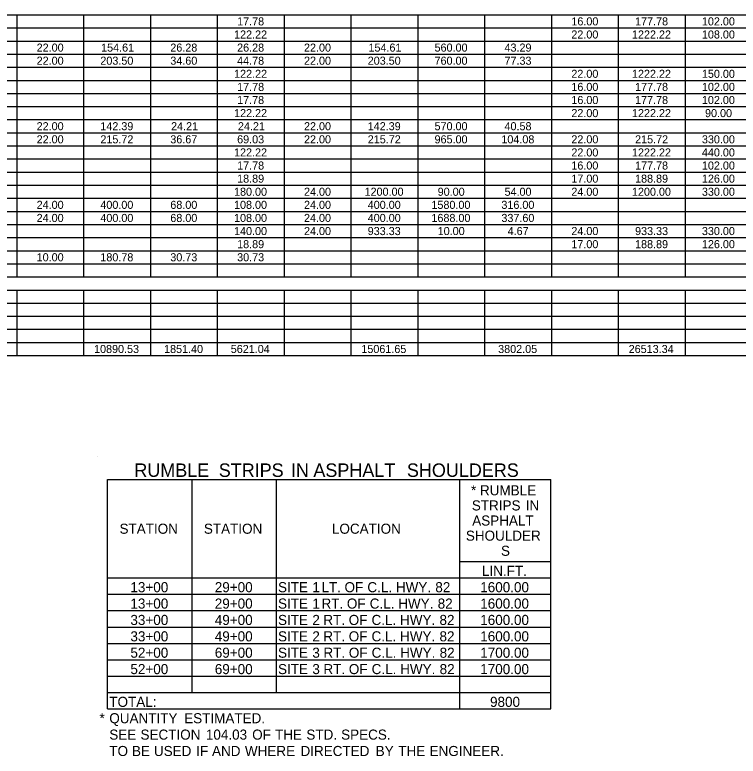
# Model space of a CAD drawing. Extents: x 977434 to 989596, y 1525697 to 1528336.
# Drawn here: x 983226 to 983656.5, y 1527372 to 1527813.2 of the extents above; entities that cross this region are included whole.
import ezdxf

# ---------------------------------------------------------------- set-up
doc = ezdxf.new("R2010")
doc.units = 0
doc.layers.add('Default', color=7, linetype='Continuous')
doc.layers.add('R_Border Prem', color=7, linetype='Continuous')

msp = doc.modelspace()

# ---------------------------------------------------------------- linework, layer by layer
at = {"layer": 'Default'}
for p, q in [((982704.74, 1527813.24), (984062.72, 1527813.24)), ((983227.34, 1527657.24), (983227.34, 1527813.24)), ((983227.34, 1527657.24), (983227.34, 1527813.24)), ((983267.12, 1527657.24), (983267.12, 1527813.24)), ((983267.12, 1527657.24), (983267.12, 1527813.24)), ((983306.9, 1527657.24), (983306.9, 1527813.24)), ((983306.9, 1527657.24), (983306.9, 1527813.24)), ((983346.68, 1527657.24), (983346.68, 1527813.24)), ((983346.68, 1527657.24), (983346.68, 1527813.24)), ((983386.46, 1527657.24), (983386.46, 1527813.24)), ((983386.46, 1527657.24), (983386.46, 1527813.24)), ((983426.24, 1527657.24), (983426.24, 1527813.24)), ((983426.24, 1527657.24), (983426.24, 1527813.24)), ((983466.02, 1527657.24), (983466.02, 1527813.24)), ((983466.02, 1527657.24), (983466.02, 1527813.24)), ((983505.8, 1527657.24), (983505.8, 1527813.24)), ((983505.8, 1527657.24), (983505.8, 1527813.24)), ((983545.58, 1527657.24), (983545.58, 1527813.24)), ((983545.58, 1527657.24), (983545.58, 1527813.24)), ((983585.36, 1527657.24), (983585.36, 1527813.24)), ((983585.36, 1527657.24), (983585.36, 1527813.24)), ((983625.14, 1527657.24), (983625.14, 1527813.24)), ((983625.14, 1527657.24), (983625.14, 1527813.24)), ((982704.74, 1527805.44), (984062.72, 1527805.44)), ((982704.74, 1527797.64), (984062.72, 1527797.64)), ((982704.74, 1527789.84), (984062.72, 1527789.84)), ((982704.74, 1527782.04), (984062.72, 1527782.04)), ((982704.74, 1527774.24), (984062.72, 1527774.24)), ((982704.74, 1527766.44), (984062.72, 1527766.44)), ((982704.74, 1527758.64), (984062.72, 1527758.64)), ((982704.74, 1527750.84), (984062.72, 1527750.84)), ((982704.74, 1527743.04), (984062.72, 1527743.04)), ((982704.74, 1527735.24), (984062.72, 1527735.24)), ((982704.74, 1527727.44), (984062.72, 1527727.44)), ((982704.74, 1527719.64), (984062.72, 1527719.64)), ((982704.74, 1527711.84), (984062.72, 1527711.84)), ((982704.74, 1527704.04), (984062.72, 1527704.04)), ((982704.74, 1527696.24), (984062.72, 1527696.24)), ((982704.74, 1527688.44), (984062.72, 1527688.44)), ((982704.74, 1527680.64), (984062.72, 1527680.64)), ((982704.74, 1527672.84), (984062.72, 1527672.84)), ((982704.74, 1527665.04), (984062.72, 1527665.04)), ((982704.74, 1527657.24), (984062.72, 1527657.24)), ((983108, 1527657.24), (983346.68, 1527657.24)), ((983346.68, 1527657.24), (983903.6, 1527657.24)), ((982704.74, 1527649.44), (984062.72, 1527649.44)), ((983227.34, 1527610.44), (983227.34, 1527649.44)), ((983227.34, 1527610.44), (983227.34, 1527649.44)), ((983267.12, 1527610.44), (983267.12, 1527649.44)), ((983267.12, 1527610.44), (983267.12, 1527649.44)), ((983306.9, 1527610.44), (983306.9, 1527649.44)), ((983306.9, 1527610.44), (983306.9, 1527649.44)), ((983346.68, 1527610.44), (983346.68, 1527649.44)), ((983346.68, 1527610.44), (983346.68, 1527649.44)), ((983386.46, 1527610.44), (983386.46, 1527649.44)), ((983386.46, 1527610.44), (983386.46, 1527649.44)), ((983426.24, 1527610.44), (983426.24, 1527649.44)), ((983426.24, 1527610.44), (983426.24, 1527649.44)), ((983466.02, 1527610.44), (983466.02, 1527649.44)), ((983466.02, 1527610.44), (983466.02, 1527649.44)), ((983505.8, 1527618.24), (983505.8, 1527649.44)), ((983505.8, 1527610.44), (983505.8, 1527649.44)), ((983545.58, 1527610.44), (983545.58, 1527649.44)), ((983545.58, 1527610.44), (983545.58, 1527649.44)), ((983585.36, 1527610.44), (983585.36, 1527649.44)), ((983585.36, 1527610.44), (983585.36, 1527649.44)), ((983625.14, 1527610.44), (983625.14, 1527649.44)), ((983625.14, 1527610.44), (983625.14, 1527649.44)), ((982704.74, 1527641.64), (984062.72, 1527641.64)), ((982704.74, 1527633.84), (984062.72, 1527633.84)), ((982704.74, 1527626.04), (984062.72, 1527626.04)), ((982704.74, 1527618.24), (984062.72, 1527618.24)), ((982704.74, 1527610.44), (984062.72, 1527610.44)), ((983281.27, 1527536.61), (983545.01, 1527536.61)), ((983281.27, 1527400.11), (983281.27, 1527536.61)), ((983281.27, 1527400.11), (983281.27, 1527536.61)), ((983331.49, 1527409.86), (983331.49, 1527536.61)), ((983331.49, 1527409.86), (983331.49, 1527536.61)), ((983381.7, 1527409.86), (983381.7, 1527536.61)), ((983381.7, 1527409.86), (983381.7, 1527536.61)), ((983490.9, 1527400.11), (983490.9, 1527536.61)), ((983545.01, 1527400.11), (983545.01, 1527536.61)), ((983545.01, 1527400.11), (983545.01, 1527536.61)), ((983490.9, 1527487.86), (983545.01, 1527487.86)), ((983281.27, 1527478.11), (983545.01, 1527478.11)), ((983281.27, 1527468.36), (983545.01, 1527468.36)), ((983281.27, 1527458.61), (983545.01, 1527458.61)), ((983281.27, 1527448.86), (983545.01, 1527448.86)), ((983281.27, 1527439.11), (983545.01, 1527439.11)), ((983281.27, 1527429.36), (983545.01, 1527429.36)), ((983281.27, 1527419.61), (983545.01, 1527419.61)), ((983281.27, 1527409.86), (983490.9, 1527409.86)), ((983281.27, 1527409.86), (983381.7, 1527409.86)), ((983381.7, 1527409.86), (983545.01, 1527409.86)), ((983281.27, 1527400.11), (983545.01, 1527400.11))]:
    msp.add_line(p, q, dxfattribs=at)
at = {"layer": 'R_Border Prem'}
msp.add_line((983275.42, 1527550.26), (983275.42, 1527550.26), dxfattribs=at)

# ---------------------------------------------------------------- texts
at = {"layer": 'Default'}
for s, height, p in [('17.78', 4.8, (983358.33, 1527806.94)), ('16.00', 4.8, (983557.24, 1527806.94)), ('177.78', 4.8, (983595.15, 1527806.94)), ('102.00', 4.8, (983634.94, 1527806.94)), ('122.22', 4.8, (983356.5, 1527799.14)), ('22.00', 4.8, (983557.24, 1527799.14)), ('1222.22', 4.8, (983593.31, 1527799.14)), ('108.00', 4.8, (983634.94, 1527799.14)), ('22.00', 4.8, (983239, 1527791.34)), ('154.61', 4.8, (983277.37, 1527791.34)), ('26.28', 4.8, (983318.55, 1527791.34)), ('26.28', 4.8, (983358.33, 1527791.34)), ('22.00', 4.8, (983398.12, 1527791.34)), ('154.61', 4.8, (983436.49, 1527791.34)), ('560.00', 4.8, (983475.82, 1527791.34)), ('43.29', 4.8, (983517.45, 1527791.34)), ('22.00', 4.8, (983239, 1527783.54)), ('203.50', 4.8, (983276.92, 1527783.54)), ('34.60', 4.8, (983318.56, 1527783.54)), ('44.78', 4.8, (983358.33, 1527783.54)), ('22.00', 4.8, (983398.12, 1527783.54)), ('203.50', 4.8, (983436.04, 1527783.54)), ('760.00', 4.8, (983475.82, 1527783.54)), ('77.33', 4.8, (983517.45, 1527783.54)), ('122.22', 4.8, (983356.5, 1527775.74)), ('22.00', 4.8, (983557.24, 1527775.74)), ('1222.22', 4.8, (983593.31, 1527775.74)), ('150.00', 4.8, (983634.94, 1527775.74)), ('17.78', 4.8, (983358.33, 1527767.94)), ('16.00', 4.8, (983557.24, 1527767.94)), ('177.78', 4.8, (983595.15, 1527767.94)), ('102.00', 4.8, (983634.94, 1527767.94)), ('17.78', 4.8, (983358.33, 1527760.14)), ('16.00', 4.8, (983557.24, 1527760.14)), ('177.78', 4.8, (983595.15, 1527760.14)), ('102.00', 4.8, (983634.94, 1527760.14)), ('122.22', 4.8, (983356.5, 1527752.34)), ('22.00', 4.8, (983557.24, 1527752.34)), ('1222.22', 4.8, (983593.31, 1527752.34)), ('90.00', 4.8, (983636.8, 1527752.34)), ('22.00', 4.8, (983239, 1527744.54)), ('142.39', 4.8, (983276.91, 1527744.54)), ('24.21', 4.8, (983319.02, 1527744.54)), ('24.21', 4.8, (983358.8, 1527744.54)), ('22.00', 4.8, (983398.12, 1527744.54)), ('142.39', 4.8, (983436.03, 1527744.54)), ('570.00', 4.8, (983475.82, 1527744.54)), ('40.58', 4.8, (983517.45, 1527744.54)), ('22.00', 4.8, (983239, 1527736.74)), ('215.72', 4.8, (983276.94, 1527736.74)), ('36.67', 4.8, (983318.55, 1527736.74)), ('69.03', 4.8, (983358.33, 1527736.74)), ('22.00', 4.8, (983398.12, 1527736.74)), ('215.72', 4.8, (983436.06, 1527736.74)), ('965.00', 4.8, (983475.82, 1527736.74)), ('104.08', 4.8, (983515.59, 1527736.74)), ('22.00', 4.8, (983557.24, 1527736.74)), ('215.72', 4.8, (983595.18, 1527736.74)), ('330.00', 4.8, (983634.94, 1527736.74)), ('122.22', 4.8, (983356.5, 1527728.94)), ('22.00', 4.8, (983557.24, 1527728.94)), ('1222.22', 4.8, (983593.31, 1527728.94)), ('440.00', 4.8, (983634.94, 1527728.94)), ('17.78', 4.8, (983358.33, 1527721.14)), ('16.00', 4.8, (983557.24, 1527721.14)), ('177.78', 4.8, (983595.15, 1527721.14)), ('102.00', 4.8, (983634.94, 1527721.14)), ('18.89', 4.8, (983358.33, 1527713.34)), ('17.00', 4.8, (983557.24, 1527713.34)), ('188.89', 4.8, (983595.15, 1527713.34)), ('126.00', 4.8, (983634.94, 1527713.34)), ('180.00', 4.8, (983356.48, 1527705.54)), ('24.00', 4.8, (983398.12, 1527705.54)), ('1200.00', 4.8, (983434.18, 1527705.54)), ('90.00', 4.8, (983477.68, 1527705.54)), ('54.00', 4.8, (983517.46, 1527705.54)), ('24.00', 4.8, (983557.24, 1527705.54)), ('1200.00', 4.8, (983593.3, 1527705.54)), ('330.00', 4.8, (983634.94, 1527705.54)), ('24.00', 4.8, (983239, 1527697.74)), ('400.00', 4.8, (983276.92, 1527697.74)), ('68.00', 4.8, (983318.56, 1527697.74)), ('108.00', 4.8, (983356.48, 1527697.74)), ('24.00', 4.8, (983398.12, 1527697.74)), ('400.00', 4.8, (983436.04, 1527697.74)), ('1580.00', 4.8, (983473.96, 1527697.74)), ('316.00', 4.8, (983515.6, 1527697.74)), ('24.00', 4.8, (983239, 1527689.94)), ('400.00', 4.8, (983276.92, 1527689.94)), ('68.00', 4.8, (983318.56, 1527689.94)), ('108.00', 4.8, (983356.48, 1527689.94)), ('24.00', 4.8, (983398.12, 1527689.94)), ('400.00', 4.8, (983436.04, 1527689.94)), ('1688.00', 4.8, (983473.96, 1527689.94)), ('337.60', 4.8, (983515.6, 1527689.94)), ('140.00', 4.8, (983356.48, 1527682.14)), ('24.00', 4.8, (983398.12, 1527682.14)), ('933.33', 4.8, (983436.03, 1527682.14)), ('10.00', 4.8, (983477.68, 1527682.14)), ('4.67', 4.8, (983519.32, 1527682.14)), ('24.00', 4.8, (983557.24, 1527682.14)), ('933.33', 4.8, (983595.15, 1527682.14)), ('330.00', 4.8, (983634.94, 1527682.14)), ('18.89', 4.8, (983358.33, 1527674.34)), ('17.00', 4.8, (983557.24, 1527674.34)), ('188.89', 4.8, (983595.15, 1527674.34)), ('126.00', 4.8, (983634.94, 1527674.34)), ('10.00', 4.8, (983239, 1527666.54)), ('180.78', 4.8, (983276.91, 1527666.54)), ('30.73', 4.8, (983318.55, 1527666.54)), ('30.73', 4.8, (983358.33, 1527666.54)), ('10890.53', 4.8, (983273.17, 1527611.94)), ('1851.40', 4.8, (983314.84, 1527611.94)), ('5621.04', 4.8, (983354.53, 1527611.94)), ('15061.65', 4.8, (983432.25, 1527611.94)), ('3802.05', 4.8, (983513.68, 1527611.94)), ('26513.34', 4.8, (983591.35, 1527611.94)), ('RUMBLE', 8, (983297.15, 1527538.21)), (' STRIPS', 8, (983344.41, 1527538.21)), (' IN', 8, (983387.34, 1527538.21)), (' ASPHALT', 8, (983400.73, 1527538.21)), (' SHOULDERS', 8, (983456.39, 1527538.21)), ('*', 6, (983497.53, 1527527.23)), (' RUMBLE', 6, (983500.61, 1527527.23)), ('STRIPS', 6, (983498, 1527518.23)), (' IN', 6, (983527.87, 1527518.23)), ('ASPHALT', 6, (983498.24, 1527509.23)), ('STATION', 6, (983288.32, 1527504.36)), ('STATION', 6, (983338.53, 1527504.36)), ('LOCATION', 6, (983414.75, 1527504.36)), ('SHOULDER', 6, (983494.45, 1527500.23)), ('S', 6, (983515.36, 1527491.23)), ('LIN.FT.', 6, (983504.04, 1527479.31)), ('13+00', 6, (983294.81, 1527469.56)), ('29+00', 6, (983345.03, 1527469.56)), ('SITE', 6, (983382.67, 1527469.56)), (' 1', 6, (983400.86, 1527469.56)), (' LT.', 6, (983406.31, 1527469.56)), (' OF', 6, (983420.01, 1527469.56)), (' C.L.', 6, (983433.6, 1527469.56)), (' HWY.', 6, (983450.57, 1527469.56)), (' 82', 6, (983474.05, 1527469.56)), ('1600.00', 6, (983503.01, 1527469.56)), ('13+00', 6, (983294.81, 1527459.81)), ('29+00', 6, (983345.03, 1527459.81)), ('SITE', 6, (983382.67, 1527459.81)), (' 1', 6, (983400.86, 1527459.81)), (' RT.', 6, (983406.31, 1527459.81)), (' OF', 6, (983421.41, 1527459.81)), (' C.L.', 6, (983435, 1527459.81)), (' HWY.', 6, (983451.96, 1527459.81)), (' 82', 6, (983475.45, 1527459.81)), ('1600.00', 6, (983503.01, 1527459.81)), ('33+00', 6, (983294.81, 1527450.06)), ('49+00', 6, (983345.03, 1527450.06)), ('SITE', 6, (983382.67, 1527450.06)), (' 2', 6, (983400.86, 1527450.06)), (' RT.', 6, (983407.41, 1527450.06)), (' OF', 6, (983422.51, 1527450.06)), (' C.L.', 6, (983436.09, 1527450.06)), (' HWY.', 6, (983453.06, 1527450.06)), (' 82', 6, (983476.54, 1527450.06)), ('1600.00', 6, (983503.01, 1527450.06)), ('33+00', 6, (983294.81, 1527440.31)), ('49+00', 6, (983345.03, 1527440.31)), ('SITE', 6, (983382.67, 1527440.31)), (' 2', 6, (983400.86, 1527440.31)), (' RT.', 6, (983407.41, 1527440.31)), (' OF', 6, (983422.51, 1527440.31)), (' C.L.', 6, (983436.09, 1527440.31)), (' HWY.', 6, (983453.06, 1527440.31)), (' 82', 6, (983476.54, 1527440.31)), ('1600.00', 6, (983503.01, 1527440.31)), ('52+00', 6, (983294.81, 1527430.56)), ('69+00', 6, (983345.03, 1527430.56)), ('SITE', 6, (983382.67, 1527430.56)), (' 3', 6, (983400.86, 1527430.56)), (' RT.', 6, (983407.47, 1527430.56)), (' OF', 6, (983422.57, 1527430.56)), (' C.L.', 6, (983436.16, 1527430.56)), (' HWY.', 6, (983453.12, 1527430.56)), (' 82', 6, (983476.61, 1527430.56)), ('1700.00', 6, (983503.01, 1527430.56)), ('52+00', 6, (983294.81, 1527420.81)), ('69+00', 6, (983345.03, 1527420.81)), ('SITE', 6, (983382.67, 1527420.81)), (' 3', 6, (983400.86, 1527420.81)), (' RT.', 6, (983407.47, 1527420.81)), (' OF', 6, (983422.57, 1527420.81)), (' C.L.', 6, (983436.16, 1527420.81)), (' HWY.', 6, (983453.12, 1527420.81)), (' 82', 6, (983476.61, 1527420.81)), ('1700.00', 6, (983503.01, 1527420.81)), ('TOTAL:', 6, (983282.25, 1527401.31)), ('9800', 6, (983508.84, 1527401.31)), ('*', 6, (983276.4, 1527391.56)), ('QUANTITY', 6, (983282.25, 1527391.56)), (' ESTIMATED.', 6, (983324.57, 1527391.56)), ('SEE', 6, (983282.25, 1527381.81)), (' SECTION', 6, (983298.58, 1527381.81)), (' 104.03', 6, (983337.49, 1527381.81)), (' OF', 6, (983365.06, 1527381.81)), (' THE', 6, (983378.65, 1527381.81)), (' STD.', 6, (983397.3, 1527381.81)), (' SPECS.', 6, (983417.99, 1527381.81)), ('TO', 6, (983282.25, 1527372.06)), (' BE', 6, (983293.52, 1527372.06)), (' USED', 6, (983306.58, 1527372.06)), (' IF', 6, (983331.76, 1527372.06)), (' AND', 6, (983341.15, 1527372.06)), (' WHERE', 6, (983360.73, 1527372.06)), (' DIRECTED', 6, (983393.82, 1527372.06)), (' BY', 6, (983438.56, 1527372.06)), (' THE', 6, (983452, 1527372.06)), (' ENGINEER.', 6, (983470.65, 1527372.06))]:
    msp.add_text(s, height=height, dxfattribs=at).set_placement(p)

doc.saveas('drawing.dxf')
